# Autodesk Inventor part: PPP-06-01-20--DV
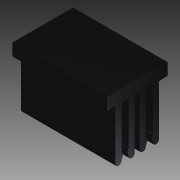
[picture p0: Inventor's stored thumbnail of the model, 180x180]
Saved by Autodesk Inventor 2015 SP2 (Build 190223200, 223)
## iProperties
Category: PARTsolutions
Company: SAMTEC
Created: 2015-08
Part Number: PPP-06-01-20--DV
Catalog Web Link: www.cadenas.de
Description: TSM Series Pick & Place Pad-TSM Series - (2,54 mm) .100" Surface Mount Terminal .025" Square Post Header
Vendor: SAMTEC
Document SubType Name: Modeling
Designer: PARTuser1
Manufacturer: SAMTEC
Mass: 0.221539 g
Surface Area: 6.25221 cm^2
Volume: 0.221539 cm^3
Density: 1 g/cm^3
Material: Allgemein
Appearance: PSOLRGB-0-0-0
PSOL_IDENT_0: {$CADENAS_DATA\23d-libs\samtec\modelling\tsm\parts\tsm_ppp.prj},205 {VTYP=3D},{NB=PPP-06-01-20--DV},
PSOL_IDENT_1: {LINA=PPP-06-01-20--DV},{NN=TSM Series Pick & Place Pad},{DATE=15.05.2015 12:28:13},{GEOMDATE=25.09.
PSOL_IDENT_2: 2014 07:23:00},{VERSION=},{LINEID=10},{LINESUBID=-1},{WBVAR=LS,POS,ROW}  {NB=PPP-06-01-20--DV},{LINA=
PSOL_IDENT_3: PPP-06-01-20--DV},{KT=DUMMY},{PN=PPP-06-01-20--DV},{LS=-01},{POS=20},{ROW=-DV},{BSH=0.230},{CSH=0.18
PSOL_IDENT_4: 0},{ESH=0.1000},{ASH=0.9000},{POSOE=2},{BSV=0.230},{CSV=0.2800}
NN: TSM Series Pick & Place Pad
NT: TSM Series - (2,54 mm) .100" Surface Mount Terminal .025" Square Post Header
NB: PPP-06-01-20--DV
NBSYN: $PN.
LINA: PPP-06-01-20--DV
LS: -01
POS: 20
ROW: -DV - Double Vertical
SUPPLIER: SAMTEC
ARTICLENO: PPP-06-01-20--DV
BOMINFO: PPP-06-01-20--DV
CREATOR: CADENAS GmbH
Title: PPP-06-01-20--DV
Author: Cadenas PARTsolutions
Comments: TSM Series - (2,54 mm) .100" Surface Mount Terminal .025" Square Post Header
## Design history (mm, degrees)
sketch "Sketch_6"
  geometry: L1 (0, 3.175)-(-1.27, 3.175); L2 (-1.27, 3.175)-(-1.27, 2.407); L3 (-1.397, 2.28)-(-6.54, 2.28); L4 (-6.54, 1.645)-(-6.477, 1.645); L5 (-5.715, 1.645)-(-1.397, 1.645); L6 (-1.27, 1.518)-(-1.27, 1.022); L7 (-1.397, 0.895)-(-5.715, 0.895); L8 (-6.477, 0.895)-(-6.522, 0.895); L9 (-6.522, 0.26)-(-1.397, 0.26); L10 (-1.27, 0.133)-(-1.27, -0.133); L11 (-1.397, -0.26)-(-6.54, -0.26); L12 (-6.54, -0.895)-(-6.477, -0.895); L13 (-5.715, -0.895)-(-1.397, -0.895); L14 (-1.27, -1.022)-(-1.27, -1.518); L15 (-1.397, -1.645)-(-5.715, -1.645); L16 (-6.477, -1.645)-(-6.54, -1.645); L17 (-6.54, -2.28)-(-1.397, -2.28); L18 (-1.27, -2.407)-(-1.27, -3.175); L19 (-1.27, -3.175)-(0, -3.175); L20 (0, -3.175)-(0, 3.175); A1 r 0.127 centre (-1.397, 2.407) between (-1.397, 2.28) and (-1.27, 2.407); A2 r 0.317 centre (-6.54, 1.963) between (-6.54, 2.28) and (-6.54, 1.645); A3 r 0.635 centre (-6.096, 2.153) between (-6.477, 1.645) and (-5.715, 1.645); A4 r 0.127 centre (-1.397, 1.518) between (-1.27, 1.518) and (-1.397, 1.645); A5 r 0.127 centre (-1.397, 1.022) between (-1.397, 0.895) and (-1.27, 1.022); A6 r 0.635 centre (-6.096, 0.387) between (-5.715, 0.895) and (-6.477, 0.895); A7 r 0.318 centre (-6.523, 0.578) between (-6.522, 0.895) and (-6.522, 0.26); A8 r 0.127 centre (-1.397, 0.133) between (-1.27, 0.133) and (-1.397, 0.26); A9 r 0.127 centre (-1.397, -0.133) between (-1.397, -0.26) and (-1.27, -0.133); A10 r 0.318 centre (-6.54, -0.578) between (-6.54, -0.26) and (-6.54, -0.895); A11 r 0.635 centre (-6.096, -0.387) between (-6.477, -0.895) and (-5.715, -0.895); A12 r 0.127 centre (-1.397, -1.022) between (-1.27, -1.022) and (-1.397, -0.895); A13 r 0.127 centre (-1.397, -1.518) between (-1.397, -1.645) and (-1.27, -1.518); A14 r 0.635 centre (-6.096, -2.153) between (-5.715, -1.645) and (-6.477, -1.645); A15 r 0.318 centre (-6.54, -1.963) between (-6.54, -1.645) and (-6.54, -2.28); A16 r 0.127 centre (-1.397, -2.407) between (-1.27, -2.407) and (-1.397, -2.28)
  constraints: 40 end point, 32 point on circle, 16 centre point
extrude "Extrusion1" join sketch "Sketch_6" stored distance "d0" = 9.906; taper "d1" = 0 deg
node "pick_place_pad_XY"
node "pick_place_pad_YZ"
node "pick_place_pad_ZX"
node "pick_place_pad_X"
node "pick_place_pad_Y"
node "pick_place_pad_Z"
node "pick_place_pad_Center"
body "Solid1"
